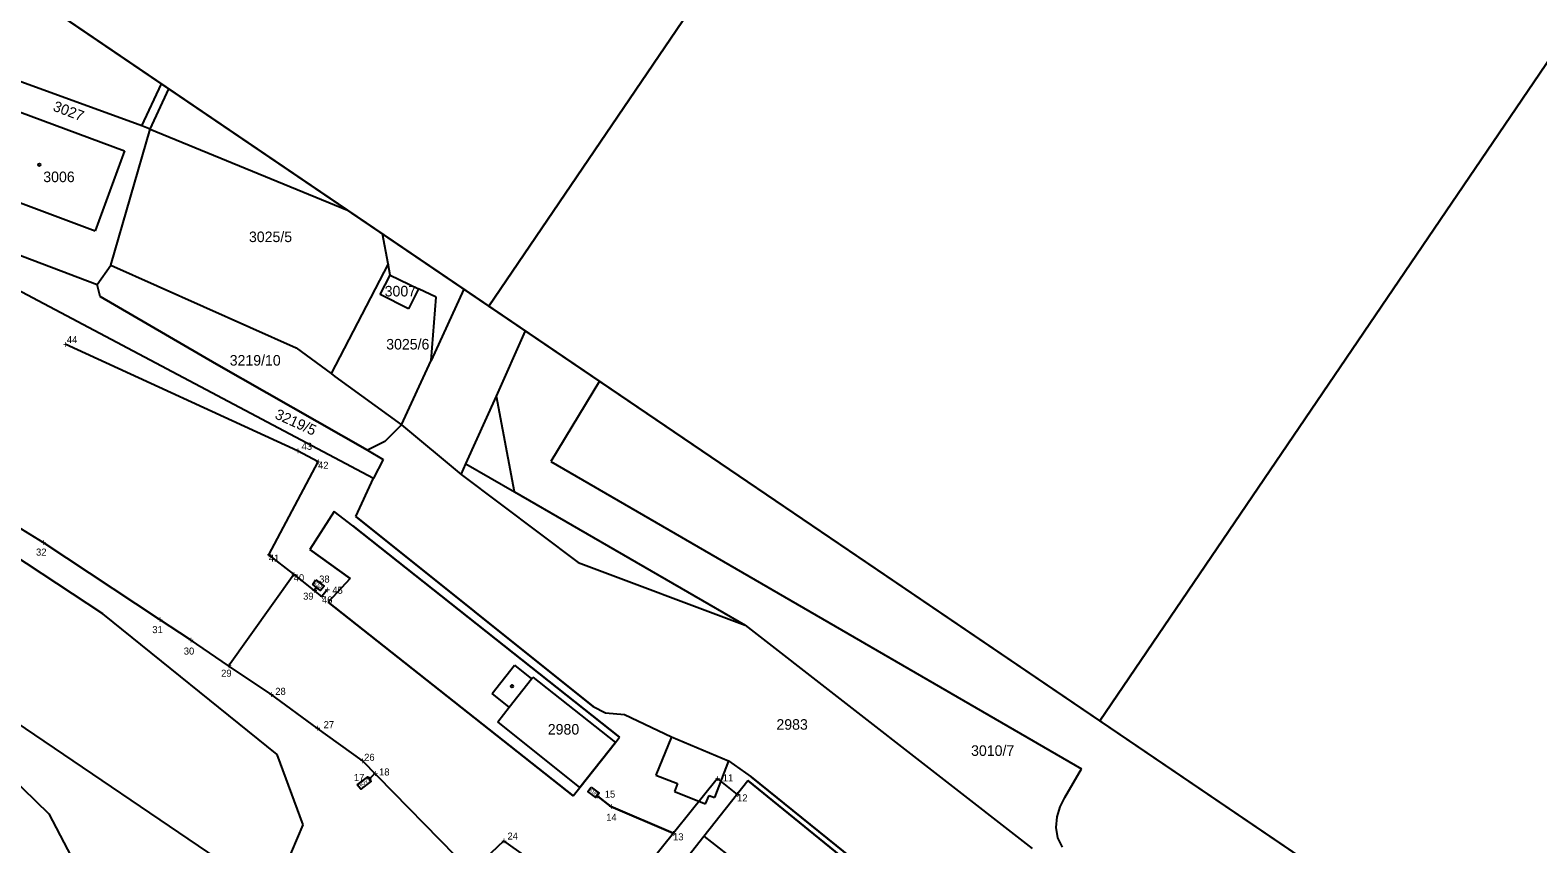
# Model space of a CAD drawing. Extents: x -621058 to -620023, y -1122866 to -1122030.
# Drawn here: x -620345 to -620130.6, y -1122701.3 to -1122585.6 of the extents above; entities that cross this region are included whole.
import ezdxf

# ---------------------------------------------------------------- set-up
doc = ezdxf.new("R2010")
doc.units = 0
for name, color, linetype in [('060604_ROZVODY_SEE', 7, 'Continuous'), ('BODY', 7, 'Continuous'), ('BODY POPIS', 7, 'Continuous'), ('RÁMY', 7, 'Continuous'), ('UZEMNĚNÍ', 7, 'Continuous'), ('Vrstva 53', 7, 'Continuous'), ('Vrstva 55', 7, 'Continuous'), ('Vrstva 56', 7, 'Continuous'), ('Vrstva 57', 7, 'Continuous')]:
    doc.layers.add(name, color=color, linetype=linetype)

msp = doc.modelspace()

# ---------------------------------------------------------------- linework, layer by layer
at = {"layer": '060604_ROZVODY_SEE'}
for p, q in [((-620304.31, -1122664.86), (-620304.64, -1122665.28)), ((-620296.8, -1122692.11), (-620296.02, -1122691.34))]:
    msp.add_line(p, q, dxfattribs=at)
for points in [[(-620243.03, -1122716), (-620248.32, -1122722.77), (-620259.89, -1122713.57), (-620277.71, -1122700.9), (-620282.35, -1122705.3), (-620297.82, -1122689.49), (-620304.22, -1122684.86), (-620310.82, -1122680.06), (-620316.82, -1122675.99), (-620322.23, -1122672.32), (-620326.63, -1122669.41), (-620343.18, -1122658.46), (-620368.5, -1122642.9), (-620411.56, -1122614.92), (-620424.16, -1122607.09), (-620443.53, -1122595), (-620444.24, -1122596.15)], [(-620316.82, -1122675.99), (-620307.57, -1122662.98), (-620311.11, -1122660.2), (-620304.11, -1122646.98), (-620307.04, -1122645.43), (-620340.05, -1122630.26)], [(-620302.83, -1122665.18), (-620303.55, -1122666.13), (-620307.57, -1122662.98)], [(-620176.84, -1122775.14), (-620205.95, -1122748.19), (-620213.63, -1122742.04), (-620221.17, -1122735.76), (-620228.34, -1122728.07), (-620234.26, -1122723.21), (-620240.17, -1122718.34), (-620248.3, -1122711.66), (-620253.57, -1122707.33), (-620257.27, -1122704.36), (-620247.33, -1122692.03), (-620244.52, -1122694.3)], [(-620253.62, -1122699.84), (-620262.46, -1122696.02), (-620264.43, -1122694.51)]]:
    msp.add_lwpolyline(points, dxfattribs=at)
for points in [[(-620304.4, -1122663.8), (-620303.26, -1122664.67), (-620303.74, -1122665.29), (-620304.87, -1122664.42)], [(-620298.52, -1122692.95), (-620297.04, -1122691.8), (-620296.56, -1122692.42), (-620298.04, -1122693.57)], [(-620265.26, -1122693.25), (-620264.13, -1122694.11), (-620264.6, -1122694.74), (-620265.74, -1122693.87)]]:
    msp.add_lwpolyline(points, close=True, dxfattribs=at)
at = {"layer": 'RÁMY'}
for points in [[(-620974.7, -1122152.91), (-620106.07, -1122742.82), (-620189.51, -1122865.67), (-621058.13, -1122275.76)], [(-620887.83, -1122211.9), (-620106.07, -1122742.82), (-620189.51, -1122865.67), (-620971.26, -1122334.75)], [(-620283.23, -1122443), (-620196.37, -1122501.99), (-620279.8, -1122624.84), (-620366.66, -1122565.85)], [(-620196.37, -1122501.99), (-620109.51, -1122560.98), (-620192.94, -1122683.83), (-620279.8, -1122624.84)], [(-620109.51, -1122560.98), (-620022.64, -1122619.97), (-620106.07, -1122742.82), (-620192.94, -1122683.83)]]:
    msp.add_lwpolyline(points, close=True, dxfattribs=at)
at = {"layer": 'UZEMNĚNÍ'}
msp.add_line((-620304.31, -1122664.86), (-620304.64, -1122665.28), dxfattribs=at)
for points in [[(-620302.83, -1122665.18), (-620303.55, -1122666.13), (-620307.57, -1122662.98), (-620311.11, -1122660.2), (-620304.11, -1122646.98), (-620307.04, -1122645.43), (-620340.05, -1122630.26)], [(-620264.43, -1122694.51), (-620262.46, -1122696.02), (-620253.62, -1122699.84)]]:
    msp.add_lwpolyline(points, dxfattribs=at)
at = {"layer": 'Vrstva 53'}
for p, q in [((-620358.11, -1122613.18), (-620335.54, -1122621.75)), ((-620334.71, -1122668.63), (-620411.71, -1122617.81)), ((-620347.83, -1122621.96), (-620296.23, -1122649.3)), ((-620335.09, -1122623.49), (-620335.54, -1122621.75)), ((-620335.09, -1122623.49), (-620318.55, -1122633.1)), ((-620318.55, -1122633.1), (-620297.09, -1122645.35)), ((-620297.09, -1122645.35), (-620294.83, -1122646.64)), ((-620294.83, -1122646.64), (-620296.23, -1122649.3)), ((-620298.73, -1122654.76), (-620296.23, -1122649.3)), ((-620301.83, -1122654.06), (-620305.28, -1122659.46)), ((-620299.15, -1122656.1), (-620301.83, -1122654.06)), ((-620298.73, -1122654.76), (-620265, -1122681.82)), ((-620299.15, -1122656.1), (-620261.22, -1122686.17)), ((-620299.56, -1122663.58), (-620305.28, -1122659.46)), ((-620299.56, -1122663.58), (-620302.66, -1122666.96)), ((-620267.81, -1122694.49), (-620302.66, -1122666.96)), ((-620309.9, -1122688.62), (-620334.71, -1122668.63)), ((-620265, -1122681.82), (-620263.22, -1122682.69)), ((-620263.22, -1122682.69), (-620260.55, -1122682.94)), ((-620260.55, -1122682.94), (-620253.83, -1122686.12)), ((-620261.82, -1122686.93), (-620266.86, -1122693.31)), ((-620261.82, -1122686.93), (-620261.22, -1122686.17)), ((-620253.83, -1122686.12), (-620245.73, -1122689.53)), ((-620306.2, -1122698.65), (-620309.9, -1122688.62)), ((-620245.73, -1122689.53), (-620242.51, -1122691.82)), ((-620267.81, -1122694.49), (-620266.86, -1122693.31)), ((-620249.26, -1122700.23), (-620243.01, -1122692.32)), ((-620226.24, -1122705.93), (-620243.01, -1122692.32)), ((-620310.57, -1122708.76), (-620306.2, -1122698.65)), ((-620251.53, -1122703.16), (-620249.26, -1122700.23))]:
    msp.add_line(p, q, dxfattribs=at)
msp.add_lwpolyline([(-620242.51, -1122691.82), (-620225.75, -1122705.35), (-620226.24, -1122705.93)], dxfattribs=at)
at = {"layer": 'Vrstva 55'}
for p, q in [((-620329.18, -1122599.21), (-620353.86, -1122590.22)), ((-620329.18, -1122599.21), (-620326.36, -1122593.22)), ((-620327.97, -1122599.65), (-620325.34, -1122593.91)), ((-620351.59, -1122595.35), (-620331.64, -1122602.77)), ((-620327.97, -1122599.65), (-620329.18, -1122599.21)), ((-620333.59, -1122619.01), (-620327.97, -1122599.65)), ((-620327.97, -1122599.65), (-620299.9, -1122611.19)), ((-620331.64, -1122602.77), (-620335.8, -1122614.14)), ((-620355.84, -1122606.66), (-620335.8, -1122614.14)), ((-620358.11, -1122613.18), (-620335.54, -1122621.75)), ((-620294.15, -1122618.83), (-620294.94, -1122614.56)), ((-620334.71, -1122668.63), (-620411.71, -1122617.81)), ((-620294.15, -1122618.83), (-620302.25, -1122634.43)), ((-620293.86, -1122620.43), (-620294.15, -1122618.83)), ((-620335.54, -1122621.75), (-620333.59, -1122619.01)), ((-620333.59, -1122619.01), (-620307.23, -1122630.79)), ((-620295.29, -1122623.2), (-620293.86, -1122620.43)), ((-620293.86, -1122620.43), (-620289.81, -1122622.36)), ((-620347.83, -1122621.96), (-620296.23, -1122649.3)), ((-620335.09, -1122623.49), (-620335.54, -1122621.75)), ((-620289.81, -1122622.36), (-620291.25, -1122625.22)), ((-620287.29, -1122623.55), (-620289.81, -1122622.36)), ((-620283.38, -1122622.41), (-620288.03, -1122632.56)), ((-620318.55, -1122633.1), (-620335.09, -1122623.49)), ((-620291.25, -1122625.22), (-620295.29, -1122623.2)), ((-620288.03, -1122632.56), (-620287.29, -1122623.55)), ((-620278.72, -1122637.63), (-620274.61, -1122628.37)), ((-620307.23, -1122630.79), (-620302.25, -1122634.43)), ((-620297.09, -1122645.35), (-620318.55, -1122633.1)), ((-620292.25, -1122641.75), (-620288.03, -1122632.56)), ((-620302.25, -1122634.43), (-620301.71, -1122634.83)), ((-620301.71, -1122634.83), (-620292.25, -1122641.75)), ((-620264.06, -1122635.53), (-620271, -1122646.92)), ((-620283.08, -1122647.29), (-620278.72, -1122637.63)), ((-620292.25, -1122641.75), (-620294.63, -1122644.08)), ((-620292.25, -1122641.75), (-620283.77, -1122648.8)), ((-620294.63, -1122644.08), (-620297.09, -1122645.35)), ((-620297.09, -1122645.35), (-620294.83, -1122646.64)), ((-620294.83, -1122646.64), (-620296.23, -1122649.3)), ((-620283.77, -1122648.8), (-620283.08, -1122647.29)), ((-620283.77, -1122648.8), (-620267.12, -1122661.31)), ((-620271, -1122646.92), (-620195.53, -1122690.65)), ((-620298.73, -1122654.76), (-620296.23, -1122649.3)), ((-620301.83, -1122654.06), (-620305.28, -1122659.46)), ((-620299.15, -1122656.1), (-620301.83, -1122654.06)), ((-620265, -1122681.82), (-620298.73, -1122654.76)), ((-620261.22, -1122686.17), (-620299.15, -1122656.1)), ((-620305.28, -1122659.46), (-620299.56, -1122663.58)), ((-620267.12, -1122661.31), (-620243.36, -1122670.23)), ((-620299.56, -1122663.58), (-620302.66, -1122666.96)), ((-620302.66, -1122666.96), (-620267.81, -1122694.49)), ((-620368.46, -1122669.58), (-620310.57, -1122708.76)), ((-620309.9, -1122688.62), (-620334.71, -1122668.63)), ((-620243.36, -1122670.23), (-620202.54, -1122702)), ((-620366.98, -1122673.23), (-620342.37, -1122697.07)), ((-620265, -1122681.82), (-620263.22, -1122682.69)), ((-620263.22, -1122682.69), (-620260.55, -1122682.94)), ((-620260.55, -1122682.94), (-620253.83, -1122686.12)), ((-620266.86, -1122693.31), (-620261.82, -1122686.93)), ((-620261.82, -1122686.93), (-620261.22, -1122686.17)), ((-620253.83, -1122686.12), (-620245.73, -1122689.53)), ((-620306.2, -1122698.65), (-620309.9, -1122688.62)), ((-620245.73, -1122689.53), (-620242.51, -1122691.82)), ((-620197.92, -1122694.75), (-620195.53, -1122690.65)), ((-620267.81, -1122694.49), (-620266.86, -1122693.31)), ((-620249.26, -1122700.23), (-620243.01, -1122692.32)), ((-620243.01, -1122692.32), (-620226.24, -1122705.93)), ((-620225.75, -1122705.35), (-620242.51, -1122691.82)), ((-620198.58, -1122696.08), (-620197.92, -1122694.75)), ((-620342.37, -1122697.07), (-620337.56, -1122706.31)), ((-620199.13, -1122698.99), (-620199.01, -1122697.5)), ((-620199.01, -1122697.5), (-620198.58, -1122696.08)), ((-620310.57, -1122708.76), (-620306.2, -1122698.65)), ((-620251.53, -1122703.16), (-620249.26, -1122700.23)), ((-620198.88, -1122700.47), (-620199.13, -1122698.99)), ((-620198.25, -1122701.83), (-620198.88, -1122700.47))]:
    msp.add_line(p, q, dxfattribs=at)
at = {"layer": 'Vrstva 56'}
for p, q in [((-620276.18, -1122651.26), (-620278.72, -1122637.63)), ((-620283.08, -1122647.29), (-620276.18, -1122651.26)), ((-620276.18, -1122651.26), (-620243.36, -1122670.23)), ((-620279.35, -1122679.94), (-620276.17, -1122675.94)), ((-620276.17, -1122675.94), (-620273.73, -1122677.87)), ((-620276.91, -1122681.88), (-620273.73, -1122677.87)), ((-620273.73, -1122677.87), (-620273.55, -1122677.64)), ((-620273.55, -1122677.64), (-620261.82, -1122686.93)), ((-620276.91, -1122681.88), (-620279.35, -1122679.94)), ((-620278.56, -1122683.97), (-620276.91, -1122681.88)), ((-620266.86, -1122693.31), (-620278.56, -1122683.97)), ((-620253.83, -1122686.12), (-620256.06, -1122691.57)), ((-620245.73, -1122689.53), (-620247.73, -1122694.76)), ((-620256.06, -1122691.57), (-620252.97, -1122692.73)), ((-620252.97, -1122692.73), (-620253.4, -1122693.88)), ((-620253.4, -1122693.88), (-620248.99, -1122695.65)), ((-620248.99, -1122695.65), (-620248.5, -1122694.45)), ((-620248.5, -1122694.45), (-620247.73, -1122694.76)), ((-620249.26, -1122700.23), (-620232.51, -1122713.28))]:
    msp.add_line(p, q, dxfattribs=at)
at = {"layer": 'Vrstva 57'}
for centre in [(-620343.73, -1122604.73), (-620276.54, -1122678.91)]:
    msp.add_circle(centre, 0.175, dxfattribs=at)

# ---------------------------------------------------------------- texts
at = {"layer": '060604_ROZVODY_SEE'}
for s, rotation, p in [('ZS1', 322.5799, (-620304.69, -1122664.32)), ('ROV1', 37.9489, (-620298.13, -1122693.4)), ('KS6', 322.5799, (-620265.61, -1122693.73))]:
    msp.add_text(s, height=0.5, rotation=rotation, dxfattribs=at).set_placement(p)
at = {"layer": 'BODY'}
for p in [(-620340.39, -1122630.76), (-620307.37, -1122645.93), (-620304.45, -1122647.48), (-620343.51, -1122658.96), (-620311.45, -1122660.7), (-620307.9, -1122663.48), (-620304.98, -1122665.78), (-620304.64, -1122665.36), (-620303.88, -1122666.63), (-620303.16, -1122665.68), (-620326.97, -1122669.91), (-620322.56, -1122672.82), (-620317.16, -1122676.49), (-620311.15, -1122680.56), (-620304.56, -1122685.36), (-620298.15, -1122689.99), (-620296.35, -1122691.83), (-620247.66, -1122692.53), (-620297.14, -1122692.61), (-620264.76, -1122695.01), (-620262.79, -1122696.52), (-620244.85, -1122694.8), (-620253.96, -1122700.34), (-620278.05, -1122701.4)]:
    msp.add_text('+', height=1, dxfattribs=at).set_placement(p)
at = {"layer": 'BODY POPIS'}
for s, p in [('44', (-620339.83, -1122630.1)), ('43', (-620306.45, -1122645.28)), ('42', (-620304.11, -1122647.98)), ('32', (-620344.21, -1122660.33)), ('41', (-620311.11, -1122661.2)), ('40', (-620307.57, -1122663.98)), ('38', (-620303.95, -1122664.17)), ('39', (-620306.23, -1122666.6)), ('45', (-620302.08, -1122665.76)), ('46', (-620303.55, -1122667.13)), ('31', (-620327.68, -1122671.36)), ('30', (-620323.2, -1122674.41)), ('29', (-620317.89, -1122677.56)), ('28', (-620310.19, -1122680.14)), ('27', (-620303.31, -1122684.88)), ('26', (-620297.55, -1122689.52)), ('17', (-620299.01, -1122692.39)), ('18', (-620295.43, -1122691.61)), ('11', (-620246.55, -1122692.45)), ('15', (-620263.33, -1122694.76)), ('12', (-620244.52, -1122695.3)), ('14', (-620263.13, -1122698.06)), ('24', (-620277.17, -1122700.73)), ('13', (-620253.62, -1122700.84))]:
    msp.add_text(s, height=1, dxfattribs=at).set_placement(p)
at = {"layer": 'Vrstva 57'}
for s, rotation, p in [('3027', 339.3, (-620341.92, -1122597)), ('3219/5', 335.5818, (-620310.37, -1122640.76))]:
    msp.add_text(s, height=1.5, rotation=rotation, dxfattribs=at).set_placement(p)
for s, p in [('3006', (-620343.18, -1122607.2)), ('3025/5', (-620313.93, -1122615.73)), ('3007', (-620294.63, -1122623.46)), ('3025/6', (-620294.41, -1122631.01)), ('3219/10', (-620316.67, -1122633.3)), ('2980', (-620271.43, -1122685.79)), ('2983', (-620238.92, -1122685.1)), ('3010/7', (-620211.24, -1122688.82))]:
    msp.add_text(s, height=1.5, dxfattribs=at).set_placement(p)

doc.saveas('drawing.dxf')
